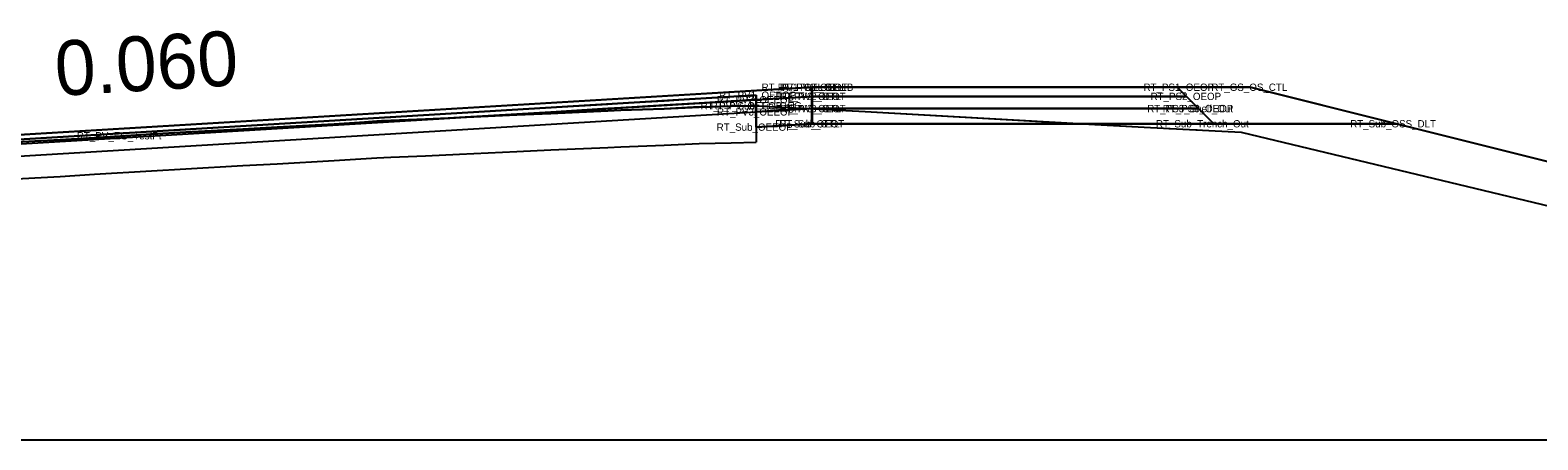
# Model space of a CAD drawing. Extents: x 2177029 to 2201446, y 59897 to 78390.
# Drawn here: x 2199287.33 to 2199328.62, y 67907.31 to 67918.52 of the extents above; entities that cross this region are included whole.
import ezdxf

# ---------------------------------------------------------------- set-up
doc = ezdxf.new("R2010")
doc.units = 0
for name, color, linetype in [('Exist Cross Section Cell', 7, 'Continuous'), ('Exist PHM Roadway Shape', 7, 'Continuous'), ('Exist XS Ground Line', 7, 'Continuous'), ('Old_Level_11', 7, 'Continuous'), ('Prop CMT Conc Surface', 7, 'Continuous'), ('Prop CMT Concrete Structures', 7, 'Continuous'), ('Prop CMT Guardrail Graphics', 7, 'Continuous'), ('Prop CMT Pvmt Course 1', 7, 'Continuous'), ('Prop CMT Pvmt Course 1 CG', 7, 'Continuous'), ('Prop CMT Pvmt Course 2', 7, 'Continuous'), ('Prop CMT Pvmt Course 2 CG', 7, 'Continuous'), ('Prop CMT Pvmt Course 3', 7, 'Continuous'), ('Prop CMT Pvmt Course 4', 7, 'Continuous'), ('Prop CMT Pvmt Surface', 7, 'Continuous'), ('Prop CMT Pvmt Wedge Surface 1', 7, 'Continuous'), ('Prop CMT Slope Grass', 7, 'Continuous'), ('Prop CMT Subgrade Earthwork', 7, 'Continuous'), ('Prop Hatching', 7, 'Continuous'), ('Prop XS Side Slope Text', 7, 'Continuous'), ('Scratch_Level_0', 7, 'Continuous'), ('Scratch_Level_9', 7, 'Continuous')]:
    doc.layers.add(name, color=color, linetype=linetype)

msp = doc.modelspace()

# ---------------------------------------------------------------- linework, layer by layer
at = {"layer": 'Exist Cross Section Cell'}
msp.add_line((2199242.732, 67907.31), (2199442.732, 67907.31), dxfattribs=at)
at = {"layer": 'Exist XS Ground Line'}
msp.add_lwpolyline([(2199286.598, 67915.436), (2199288.153, 67915.523), (2199289.095, 67915.581), (2199290.653, 67915.675), (2199291.593, 67915.729), (2199293.152, 67915.818), (2199294.09, 67915.868), (2199295.653, 67915.953), (2199296.821, 67916.032), (2199297.209, 67916.048), (2199298.153, 67916.084), (2199299.085, 67916.129), (2199300.653, 67916.203), (2199301.584, 67916.247), (2199303.153, 67916.316), (2199303.502, 67916.331), (2199304.696, 67916.375), (2199305.653, 67916.42), (2199306.525, 67916.444), (2199307.213, 67916.454), (2199310.192, 67916.296), (2199317.833, 67915.868), (2199320.495, 67915.731), (2199330.337, 67913.369)], dxfattribs=at)
at = {"layer": 'Prop CMT Conc Surface'}
for points in [[(2199308.732, 67916.711), (2199308.732, 67916.961)], [(2199272.732, 67914.676), (2199307.213, 67916.745)], [(2199307.213, 67916.745), (2199307.213, 67916.62)], [(2199307.213, 67916.62), (2199308.732, 67916.711)]]:
    msp.add_lwpolyline(points, dxfattribs=at)
at = {"layer": 'Prop CMT Concrete Structures'}
for p, q in [((2199272.732, 67914.801), (2199308.732, 67916.961)), ((2199308.732, 67916.961), (2199308.741, 67916.962)), ((2199308.741, 67916.962), (2199308.742, 67916.962))]:
    msp.add_line(p, q, dxfattribs=at)
at = {"layer": 'Prop CMT Guardrail Graphics'}
for points in [[(2199308.732, 67916.378), (2199308.732, 67916.961)], [(2199272.732, 67914.218), (2199308.732, 67916.378)]]:
    msp.add_lwpolyline(points, dxfattribs=at)
at = {"layer": 'Prop CMT Pvmt Course 1'}
for points in [[(2199307.213, 67916.454), (2199307.213, 67916.454), (2199306.944, 67916.447), (2199306.834, 67916.449), (2199306.525, 67916.444), (2199305.653, 67916.42), (2199305.497, 67916.412), (2199304.696, 67916.375), (2199303.502, 67916.331), (2199303.153, 67916.316), (2199301.584, 67916.247), (2199300.653, 67916.203), (2199299.085, 67916.129), (2199298.78, 67916.114)], [(2199299.085, 67916.133), (2199300.653, 67916.227), (2199301.584, 67916.283), (2199303.153, 67916.377), (2199303.502, 67916.398), (2199304.696, 67916.469), (2199305.497, 67916.517), (2199305.653, 67916.527), (2199306.525, 67916.579), (2199306.834, 67916.598), (2199306.944, 67916.604), (2199307.213, 67916.62), (2199307.213, 67916.62)], [(2199307.213, 67916.62), (2199307.213, 67916.454)], [(2199298.78, 67916.114), (2199299.085, 67916.133)]]:
    msp.add_lwpolyline(points, dxfattribs=at)
at = {"layer": 'Prop CMT Pvmt Course 1 CG'}
for points in [[(2199308.742, 67916.378), (2199319.325, 67916.378)], [(2199308.742, 67915.962), (2199308.742, 67916.378)], [(2199319.325, 67916.378), (2199319.325, 67916.378)], [(2199319.325, 67916.378), (2199319.742, 67915.962)], [(2199319.742, 67915.962), (2199308.742, 67915.962)]]:
    msp.add_lwpolyline(points, dxfattribs=at)
at = {"layer": 'Prop CMT Pvmt Course 2'}
for points in [[(2199307.213, 67916.287), (2199308.732, 67916.378)], [(2199308.732, 67916.378), (2199308.742, 67916.378)], [(2199308.732, 67915.961), (2199308.732, 67916.378)], [(2199308.732, 67916.378), (2199308.732, 67915.961)], [(2199308.742, 67916.378), (2199308.742, 67915.962)], [(2199307.213, 67915.87), (2199307.213, 67916.287)], [(2199308.732, 67915.961), (2199307.213, 67915.87)], [(2199308.742, 67915.962), (2199308.732, 67915.961)]]:
    msp.add_lwpolyline(points, dxfattribs=at)
at = {"layer": 'Prop CMT Pvmt Course 2 CG'}
for points in [[(2199272.732, 67914.801), (2199308.732, 67916.961)], [(2199308.732, 67916.961), (2199308.742, 67916.962)], [(2199308.732, 67916.711), (2199308.732, 67916.961)], [(2199308.732, 67916.961), (2199308.732, 67916.711)], [(2199308.742, 67916.962), (2199308.742, 67916.712)], [(2199307.213, 67916.745), (2199272.732, 67914.676)], [(2199307.213, 67916.62), (2199307.213, 67916.745)], [(2199308.732, 67916.711), (2199307.213, 67916.62)], [(2199308.742, 67916.712), (2199308.732, 67916.711)]]:
    msp.add_lwpolyline(points, dxfattribs=at)
at = {"layer": 'Prop CMT Pvmt Course 3'}
for points in [[(2199307.213, 67915.87), (2199307.198, 67916.453)], [(2199307.213, 67915.87), (2199308.732, 67915.961)], [(2199308.732, 67915.961), (2199308.742, 67915.962)], [(2199308.742, 67915.962), (2199319.742, 67915.962)], [(2199319.742, 67915.962), (2199324.742, 67915.962)]]:
    msp.add_lwpolyline(points, dxfattribs=at)
at = {"layer": 'Prop CMT Pvmt Course 4'}
msp.add_lwpolyline([(2199308.742, 67916.962), (2199318.741, 67916.962)], dxfattribs=at)
at = {"layer": 'Prop CMT Pvmt Surface'}
for points in [[(2199286.598, 67915.508), (2199288.153, 67915.602), (2199289.095, 67915.658), (2199290.653, 67915.752), (2199291.593, 67915.808), (2199293.152, 67915.902), (2199294.09, 67915.958), (2199295.653, 67916.052), (2199296.487, 67916.102), (2199296.709, 67916.115), (2199296.821, 67916.122), (2199296.955, 67916.13), (2199297.208, 67916.145), (2199298.153, 67916.202), (2199299.085, 67916.258), (2199300.653, 67916.352), (2199301.584, 67916.408), (2199303.153, 67916.502), (2199303.502, 67916.523), (2199304.696, 67916.594), (2199305.497, 67916.642), (2199305.653, 67916.652), (2199306.525, 67916.704), (2199306.834, 67916.723), (2199306.944, 67916.729), (2199307.213, 67916.745), (2199307.213, 67916.745)], [(2199307.213, 67916.62), (2199307.213, 67916.62), (2199306.944, 67916.604), (2199306.834, 67916.598), (2199306.525, 67916.579), (2199305.653, 67916.527), (2199305.497, 67916.517), (2199304.696, 67916.469), (2199303.502, 67916.398), (2199303.153, 67916.377), (2199301.584, 67916.283), (2199300.653, 67916.227), (2199299.085, 67916.133), (2199298.78, 67916.114), (2199298.153, 67916.084), (2199297.208, 67916.048), (2199296.955, 67916.038), (2199296.821, 67916.032), (2199296.709, 67916.025), (2199296.487, 67916.01), (2199295.653, 67915.953), (2199294.09, 67915.868), (2199293.152, 67915.818), (2199291.593, 67915.729), (2199290.653, 67915.675), (2199289.095, 67915.581), (2199288.153, 67915.523), (2199286.598, 67915.436)], [(2199307.213, 67916.745), (2199307.213, 67916.62)]]:
    msp.add_lwpolyline(points, dxfattribs=at)
at = {"layer": 'Prop CMT Pvmt Wedge Surface 1'}
for p, q in [((2199307.213, 67916.454), (2199307.213, 67915.454)), ((2199298.153, 67915.084), (2199299.085, 67915.129)), ((2199299.085, 67915.129), (2199300.653, 67915.203)), ((2199300.653, 67915.203), (2199301.584, 67915.247)), ((2199301.584, 67915.247), (2199303.153, 67915.316)), ((2199303.153, 67915.316), (2199303.502, 67915.331)), ((2199303.502, 67915.331), (2199304.696, 67915.375)), ((2199304.696, 67915.375), (2199305.653, 67915.42)), ((2199305.653, 67915.42), (2199306.525, 67915.444)), ((2199306.525, 67915.444), (2199307.213, 67915.454)), ((2199290.653, 67914.675), (2199291.593, 67914.729)), ((2199291.593, 67914.729), (2199293.152, 67914.818)), ((2199293.152, 67914.818), (2199294.09, 67914.868)), ((2199294.09, 67914.868), (2199295.653, 67914.953)), ((2199295.653, 67914.953), (2199296.821, 67915.032)), ((2199296.821, 67915.032), (2199297.209, 67915.048)), ((2199297.209, 67915.048), (2199298.153, 67915.084)), ((2199286.598, 67914.436), (2199288.153, 67914.523)), ((2199288.153, 67914.523), (2199289.095, 67914.581)), ((2199289.095, 67914.581), (2199290.653, 67914.675))]:
    msp.add_line(p, q, dxfattribs=at)
at = {"layer": 'Prop CMT Slope Grass'}
for points in [[(2199307.213, 67916.62), (2199308.732, 67916.711)], [(2199307.213, 67916.287), (2199307.213, 67916.62)], [(2199308.732, 67916.378), (2199307.213, 67916.287)], [(2199308.732, 67916.711), (2199308.742, 67916.712)], [(2199308.732, 67916.378), (2199308.732, 67916.711)], [(2199308.732, 67916.711), (2199308.732, 67916.378)], [(2199308.742, 67916.378), (2199308.732, 67916.378)], [(2199308.742, 67916.712), (2199308.742, 67916.378)]]:
    msp.add_lwpolyline(points, dxfattribs=at)
at = {"layer": 'Prop CMT Subgrade Earthwork'}
for points in [[(2199308.732, 67916.711), (2199308.732, 67916.961)], [(2199272.732, 67914.551), (2199308.732, 67916.711)]]:
    msp.add_lwpolyline(points, dxfattribs=at)
at = {"layer": 'Prop Hatching'}
msp.add_lwpolyline([(2199318.741, 67916.962), (2199320.742, 67916.962), (2199351.55, 67909.26)], dxfattribs=at)
at = {"layer": 'Prop XS Side Slope Text'}
msp.add_lwpolyline([(2199286.598, 67915.436), (2199288.153, 67915.523), (2199289.095, 67915.581), (2199290.653, 67915.675), (2199291.593, 67915.729), (2199293.152, 67915.818), (2199294.09, 67915.868), (2199295.653, 67915.953), (2199296.821, 67916.032), (2199297.209, 67916.048), (2199298.153, 67916.084), (2199299.085, 67916.129), (2199300.653, 67916.203), (2199301.584, 67916.247), (2199303.153, 67916.316), (2199303.502, 67916.331), (2199304.696, 67916.375), (2199305.653, 67916.42), (2199306.525, 67916.444), (2199307.198, 67916.453), (2199310.192, 67916.296), (2199316.15, 67915.962), (2199319.742, 67915.962), (2199324.742, 67915.962), (2199320.742, 67916.962), (2199318.741, 67916.962), (2199308.742, 67916.962), (2199272.732, 67914.801)], dxfattribs=at)
for points in [[(2199307.198, 67916.453), (2199310.192, 67916.296), (2199316.15, 67915.962), (2199308.732, 67915.961), (2199307.213, 67915.87)], [(2199341.611, 67910.549), (2199344.504, 67911.022), (2199324.742, 67915.962), (2199319.742, 67915.962), (2199316.15, 67915.962), (2199317.833, 67915.868), (2199320.495, 67915.731), (2199330.337, 67913.369)]]:
    msp.add_lwpolyline(points, close=True, dxfattribs=at)
at = {"layer": 'Scratch_Level_0'}
for points in [[(2199308.742, 67916.712), (2199318.992, 67916.712), (2199319.325, 67916.378)], [(2199308.742, 67916.378), (2199308.742, 67916.712)], [(2199319.325, 67916.378), (2199308.742, 67916.378)]]:
    msp.add_lwpolyline(points, dxfattribs=at)
at = {"layer": 'Scratch_Level_9'}
for points in [[(2199308.742, 67916.962), (2199318.741, 67916.962), (2199318.992, 67916.712)], [(2199308.742, 67916.712), (2199308.742, 67916.962)], [(2199318.992, 67916.712), (2199308.742, 67916.712)]]:
    msp.add_lwpolyline(points, dxfattribs=at)

# ---------------------------------------------------------------- texts
at = {"layer": 'Exist PHM Roadway Shape'}
for s, p in [('RT_PV1_OEEOP', (2199306.196, 67916.645)), ('RT_PV1_OTL SE LB', (2199307.359, 67916.862)), ('RT_PV2_OEOT', (2199307.745, 67916.611)), ('RT_PV1_OEOT', (2199307.801, 67916.861)), ('RT_PV2_OTL', (2199307.852, 67916.612)), ('RT_PV1_OTL', (2199307.909, 67916.862)), ('RT_PS1_OEOP', (2199317.817, 67916.862)), ('RT_PS2_OEOP', (2199318.011, 67916.612)), ('RT_GS_OS_CTL', (2199319.674, 67916.862)), ('RT_PV_Sub_Tie_Out', (2199305.688, 67916.353)), ('RT_PV_OEEOP_EG', (2199305.963, 67916.354)), ('RT_PV2_OEEOP', (2199306.139, 67916.52)), ('RT_PV3_OEEOP', (2199306.139, 67916.187)), ('RT_PV3_OEOT', (2199307.745, 67916.278)), ('RT_PV3_OTL', (2199307.852, 67916.278)), ('RT_PS3_Shelf_Out', (2199317.919, 67916.278)), ('RT_PS3_OEOP', (2199318.344, 67916.278)), ('RT_Sub_OEEOP', (2199306.13, 67915.77)), ('RT_Sub_OEOT', (2199307.735, 67915.861)), ('RT_Sub_OTL', (2199307.843, 67915.862)), ('RT_Sub_Trench_Out', (2199318.158, 67915.862)), ('RT_Sub_OSS_DLT', (2199323.478, 67915.862)), ('RT_PV_EG_TestPt', (2199288.609, 67915.534))]:
    msp.add_text(s, height=0.2, dxfattribs=at).set_placement(p)
at = {"layer": 'Old_Level_11'}
msp.add_text('0.060', height=1.5, rotation=3.4336, dxfattribs=at).set_placement((2199288.052, 67916.722))

doc.saveas('drawing.dxf')
